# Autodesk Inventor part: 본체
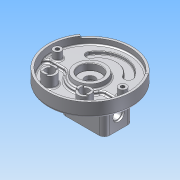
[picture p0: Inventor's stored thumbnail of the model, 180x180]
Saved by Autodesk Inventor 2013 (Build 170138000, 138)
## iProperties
Company: 한국ATC센터
Created: 2015-04
Part Number: 본체
Document SubType Name: Modeling
Designer: KYOUNG IL JANG
Density: 2.71 g/cm^3
Material: 알루미늄-6061
Mass: 1340.83 g
Surface Area: 1387.38 cm^2
Volume: 494.771 cm^3
Author: KYOUNG IL JANG
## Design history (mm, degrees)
sketch "스케치1"
  geometry: L1 (-59, -19)-(-59, 19); L2 (59, 19)-(59, -19); L3 (-41, 19)-(-41, -19); L4 (41, -19)-(41, 19); L5 (38.527, 33.023)-(55.442, 39.179); L6 (-38.527, 33.023)-(-55.442, 39.179); C1 r 90 at (0, 0); C2 r 95 at (0, 0); A1 r 59 centre (0, 19) between (59, 19) and (-59, 19); A2 r 59 centre (0, -19) between (-59, -19) and (59, -19); A3 r 41 centre (0, -19) between (-41, -19) and (41, -19); A4 r 41 centre (0, 19) between (41, 19) and (-41, 19); 2 further points
  constraints: 12 end point, 12 point on circle, 6 centre point, 4 tangent, 2 parallel, 2 point on line, 1 coincident, 1 horizontal alignment, 1 midpoint, 1 vertical, 1 vertical alignment, 3 other
  dimensions: "d2" = 180 diameter of C1; "d3" = 156 dimension on A2 A1; "d4" = 118 distance between parallel lines of L2 L1; "d5" = 18 distance between parallel lines of L2 L4; "d8" = 190 diameter of C2; "d124" = 110 deg dimension on A1.centre point (0, 0) L5.end; "d125" = 140 deg angle of L5 L6
extrude "돌출1" new body sketch "스케치1" distance "d6" = 14; taper "d7" = 0 deg
extrude "돌출2" join sketch "스케치1" distance "d9" = 13; taper "d10" = 0 deg
extrude "돌출3" cut sketch "스케치1" distance "d11" = 7; taper "d12" = 0 deg
sketch "스케치2"
  geometry: C1 r 11.5 at (0, 0); 1 further point
  constraints: 1 centre point, 1 coincident
  dimensions: "d13" = 23 diameter of C1
extrude "돌출4" cut sketch "스케치2" stored distance "d14" = 7; taper "d15" = 0 deg
fillet "모깎기1"
fillet "모깎기2"
sketch "스케치3"
  geometry: L1 (-73.724, 51.622)-(-77.819, 54.49); L2 (73.724, 51.622)-(77.819, 54.49); L3 (0, 0)-(0, -90); A1 r 95 centre (0, 0) between (-77.819, 54.49) and (77.819, 54.49) reference; A2 r 90 centre (0, 0) between (-73.724, 51.622) and (73.724, 51.622) reference; 1 further point
  constraints: 6 end point, 5 point on circle, 1 point on line, 1 vertical, 1 other
  dimensions: "d16" = 250 deg dimension on L2 L1
extrude "돌출5" join sketch "스케치3" distance "d17" = 5; taper "d18" = 0 deg
hole "구멍1" diameter "d21" = 50; stored, may be unused: countersink angle "d25" = 90 deg, drill point angle "d27" = 0 deg; dims "d19" = 10, "d20" = 10, "d22" = 6, "d23" = 4, "d24" = 2, "d26" = 5
fillet "모깎기3" dims "d28" = 0.3
fillet "모깎기5" dims "d30" = 3
sketch "스케치4"
  geometry: C1 r 35 at (0, 0); C2 r 25 at (0, 0); 1 further point
  constraints: 2 centre point, 1 coincident
  dimensions: "d32" = 70 diameter of C1 (derived); "d36" = 10 radial gap between concentric circles of C1 C2
extrude "돌출6" join sketch "스케치4" distance "d33" = 10; taper "d34" = 0 deg
feature "면 기울기2" dims angle "d37" = 10 deg
chamfer "모따기1" distance "d39" = 1; stored, may be unused: second distance "d40" = 2, angle "d41" = 45 deg
fillet "모깎기7" dims "d42" = 5
sketch "스케치5"
  geometry: L1 (-40.249, -12)-(-89.196, -12); L2 (40.249, -12)-(89.196, -12); A1 r 90 centre (0, 0) between (-89.196, -12) and (89.196, -12) reference; A2 r 42 centre (0, 0) between (-40.249, -12) and (40.249, -12); 1 further point
  constraints: 4 end point, 4 point on circle, 1 centre point, 1 collinear, 1 horizontal, 1 point on line
  dimensions: "d43" = 48 radial gap between concentric circles of A1 A2; "d44" = 12 distance from line of point (0, 0) L1
extrude "돌출7" cut sketch "스케치5" stored distance "d45" = 10; taper "d46" = 0 deg
fillet "모깎기8" dims "d47" = 10
chamfer "모따기2" distance "d49" = 1; stored, may be unused: second distance "d50" = 2, angle "d51" = 45 deg
sketch "스케치8"
  geometry: C1 r 9 at (74, 0); C2 r 9 at (-74, 0); A1 r 74 centre (0, 0) between (74, 0) and (-74, 0); 1 further point
  constraints: 3 centre point, 2 horizontal alignment, 2 point on circle, 1 coincident, 1 equal radius
  dimensions: "d64" = 18 diameter of C1; "d65" = 148 diameter of A1
extrude "돌출9" join sketch "스케치8" stored distance "d66" = 5; taper "d67" = 0 deg
sketch "스케치11"
  geometry: C1 r 15 at (40, -52); C2 r 15 at (-40, -52); 1 further point
  constraints: 2 centre point, 1 equal radius, 1 horizontal alignment
  dimensions: "d82" = 52 vertical distance of point (0, 0) C1.centre; "d83" = 30 diameter of C1; "d84" = 80 distance of C2.centre C1.centre; "d85" = 40 horizontal distance of point (0, 0) C1.centre (= 0.5 x d84)
extrude "돌출10" join sketch "스케치11" stored distance "d86" = 10; taper "d87" = 0 deg
node "구멍3"
node "구멍5"
hole "구멍6" diameter "d92" = 20; stored, may be unused: countersink angle "d96" = 90 deg, drill point angle "d98" = 118 deg; dims "d90" = 10, "d91" = 10, "d93" = 6, "d94" = 4, "d95" = 2, "d97" = 8
hole "구멍7" diameter "d101" = 20; stored, may be unused: countersink angle "d105" = 90 deg, drill point angle "d107" = 118 deg; dims "d99" = 10, "d100" = 10, "d102" = 6, "d103" = 4, "d104" = 2, "d106" = 8
fillet "모깎기13" dims "d108" = 3
sketch "스케치13"
  geometry: L1 (-20.252, -58)-(-26, -58); L2 (-42, -58)-(-47.748, -58); L3 (-20.252, -46)-(-26, -46); L4 (-42, -46)-(-47.748, -46); L5 (-108, -65.748)-(-108, -60); L6 (-108, -44)-(-108, -38.252); L7 (-120, -44)-(-120, -38.252); L8 (-120, -60)-(-120, -65.748); A1 r 15 centre (-34, -52) between (-20.252, -58) and (-47.748, -58) reference; A2 r 10 centre (-34, -52) between (-26, -58) and (-42, -58) reference; A3 r 15 centre (-114, -52) between (-108, -65.748) and (-108, -38.252) reference; A4 r 10 centre (-114, -52) between (-108, -60) and (-108, -44) reference; 1 further point
  constraints: 16 end point, 16 point on circle, 3 equal length, 3 point on line, 2 collinear, 1 horizontal, 1 perpendicular
  dimensions: "d114" = 12 distance between parallel lines of L4 L2; "d115" = 6 distance from line of A1.centre L2 (= 0.5 x d114); "d116" = 12 distance between parallel lines of L8 L5 (= d114); "d117" = 6 distance from line of A3.centre L5 (= d115)
extrude "돌출12" join sketch "스케치13" distance "d118" = 3; taper "d119" = 0 deg
fillet "모깎기14" dims "d120" = 1
sketch "스케치14"
  geometry: L1 (23, 32.5)-(-53, 32.5); L2 (-65, 20.5)-(-65, -20.5); L3 (-53, -32.5)-(23, -32.5); L4 (35, -20.5)-(35, 20.5); L5 (30, 20.5)-(30, -20.5); L6 (23, -27.5)-(-53, -27.5); L7 (-60, -20.5)-(-60, 20.5); L8 (-53, 27.5)-(23, 27.5); A1 r 12 centre (-53, -20.5) between (-65, -20.5) and (-53, -32.5); A2 r 12 centre (-53, 20.5) between (-53, 32.5) and (-65, 20.5); A3 r 12 centre (23, 20.5) between (35, 20.5) and (23, 32.5); A4 r 12 centre (23, -20.5) between (23, -32.5) and (35, -20.5); A5 r 7 centre (23, -20.5) between (23, -27.5) and (30, -20.5); A6 r 7 centre (-53, -20.5) between (-60, -20.5) and (-53, -27.5); A7 r 7 centre (-53, 20.5) between (-53, 27.5) and (-60, 20.5); A8 r 7 centre (23, 20.5) between (30, 20.5) and (23, 27.5); A9 r 6 centre (-23, -25) between (-17.546, -27.5) and (-28.454, -27.5); A10 r 6 centre (-23, 25) between (-28.454, 27.5) and (-17.546, 27.5); 6 further points
  constraints: 20 point on circle, 16 end point, 12 point on line, 10 centre point, 8 tangent, 4 equal radius, 4 parallel, 2 perpendicular, 1 horizontal, 1 horizontal alignment, 1 midpoint, 1 vertical alignment, 7 other
  dimensions: "d126" = 35 distance from line of point (0, 0) L4; "d127" = 65 distance of point (35, -32.5) point (35, 32.5); "d128" = 100 distance of point (35, 32.5) point (-65, 32.5); "d132" = 12 radius of A1; "d133" = 5 distance between parallel lines of L5 L4; "d141" = 42 distance from line of A9.centre L2; "d142" = 12 diameter of A9; "d143" = 50 distance of A10.centre A9.centre; "d144" = 25 vertical distance of point (0, 0) A9.centre (= 0.5 x d143)
extrude "돌출13" join sketch "스케치14" distance "d130" = 58; taper "d131" = 0 deg
fillet "모깎기16" dims "d145" = 3
hole "구멍8" diameter "d148" = 4.134; stored, may be unused: countersink angle "d152" = 90 deg, drill point angle "d154" = 118 deg; dims "d146" = 10, "d147" = 10, "d149" = 12, "d150" = 4, "d151" = 2, "d153" = 15
hole "구멍9" diameter "d157" = 4.134; stored, may be unused: countersink angle "d161" = 90 deg, drill point angle "d163" = 118 deg; dims "d155" = 10, "d156" = 10, "d158" = 12, "d159" = 4, "d160" = 2, "d162" = 15
sketch "스케치17"
  geometry: L1 (-58, 110.5)-(-58, -69.5) reference; C1 r 15 at (-29.5, 20.5); 1 further point
  constraints: 1 centre point, 1 horizontal alignment
  dimensions: "d164" = 28.5 distance from line of C1.centre L1; "d165" = 30 diameter of C1
extrude "돌출16" join sketch "스케치17" distance "d166" = 28; taper "d167" = 0 deg
fillet "모깎기17" dims "d168" = 1
hole "구멍10" diameter "d171" = 22; stored, may be unused: countersink angle "d175" = 90 deg, drill point angle "d177" = 118 deg; dims "d169" = 10, "d170" = 10, "d172" = 12, "d173" = 26, "d174" = 4, "d176" = 15
node "솔리드1"
sketch "스케치9"
  geometry: 1 further point
hole "구멍2" sketch "스케치9" diameter "d68" = 8.376; stored, may be unused: countersink angle "d72" = 90 deg, drill point angle "d74" = 120 deg; dims "d69" = 16, "d70" = 4, "d71" = 2, "d73" = 21
sketch "스케치10"
  geometry: 1 further point
hole "구멍4" sketch "스케치10" diameter "d75" = 8.376; stored, may be unused: countersink angle "d79" = 90 deg, drill point angle "d81" = 120 deg; dims "d76" = 16, "d77" = 4, "d78" = 2, "d80" = 21
